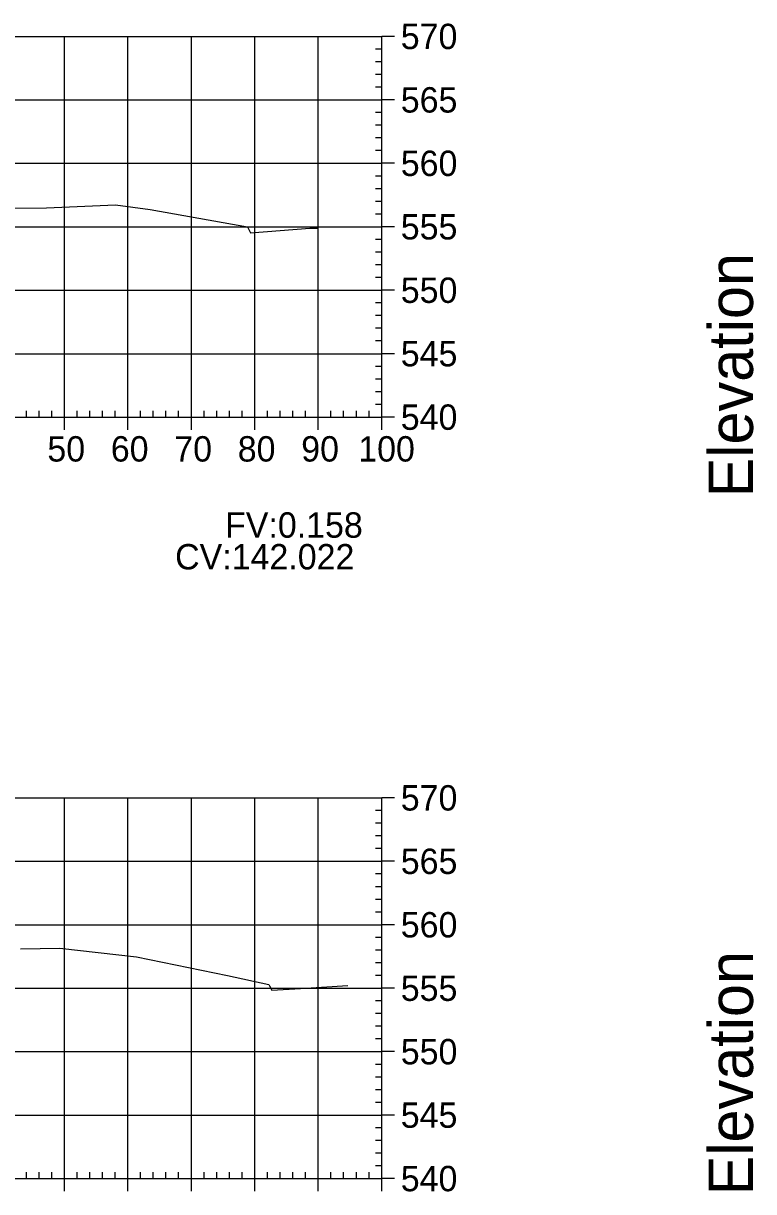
# Model space of a CAD drawing. Extents: x 704834 to 709892, y 372981 to 377533.
# Drawn here: x 707005.4 to 707120.5, y 373850.8 to 374034.9 of the extents above; entities that cross this region are included whole.
import ezdxf

# ---------------------------------------------------------------- set-up
doc = ezdxf.new("R2010")
doc.units = 0
for name, color, linetype in [('57', 7, 'Continuous'), ('59', 7, 'Continuous'), ('60', 7, 'Continuous'), ('Existing', 7, 'Continuous')]:
    doc.layers.add(name, color=color, linetype=linetype)

msp = doc.modelspace()

# ---------------------------------------------------------------- linework, layer by layer
at = {"layer": '57'}
for p, q in [((706861.87, 374032.82), (707061.87, 374032.82)), ((707011.87, 373972.82), (707011.87, 374032.82)), ((707021.87, 373972.82), (707021.87, 374032.82)), ((707031.87, 373972.82), (707031.87, 374032.82)), ((707041.87, 373972.82), (707041.87, 374032.82)), ((707051.87, 373972.82), (707051.87, 374032.82)), ((707061.87, 373972.82), (707061.87, 374032.82)), ((707061.87, 373972.82), (707061.87, 374032.82)), ((707063.87, 374032.82), (707061.87, 374032.82)), ((707061.87, 374030.82), (707060.87, 374030.82)), ((707061.87, 374028.82), (707060.87, 374028.82)), ((707061.87, 374026.82), (707060.87, 374026.82)), ((707061.87, 374024.82), (707060.87, 374024.82)), ((706861.87, 374022.82), (707061.87, 374022.82)), ((707063.87, 374022.82), (707061.87, 374022.82)), ((707061.87, 374020.82), (707060.87, 374020.82)), ((707061.87, 374018.82), (707060.87, 374018.82)), ((707061.87, 374016.82), (707060.87, 374016.82)), ((707061.87, 374014.82), (707060.87, 374014.82)), ((706861.87, 374012.82), (707061.87, 374012.82)), ((707063.87, 374012.82), (707061.87, 374012.82)), ((707061.87, 374010.82), (707060.87, 374010.82)), ((707061.87, 374008.82), (707060.87, 374008.82)), ((707061.87, 374006.82), (707060.87, 374006.82)), ((707061.87, 374004.82), (707060.87, 374004.82)), ((706861.87, 374002.82), (707061.87, 374002.82)), ((707063.87, 374002.82), (707061.87, 374002.82)), ((707061.87, 374000.82), (707060.87, 374000.82)), ((707061.87, 373998.82), (707060.87, 373998.82)), ((707061.87, 373996.82), (707060.87, 373996.82)), ((707061.87, 373994.82), (707060.87, 373994.82)), ((706861.87, 373992.82), (707061.87, 373992.82)), ((707063.87, 373992.82), (707061.87, 373992.82)), ((707061.87, 373990.82), (707060.87, 373990.82)), ((707061.87, 373988.82), (707060.87, 373988.82)), ((707061.87, 373986.82), (707060.87, 373986.82)), ((707061.87, 373984.82), (707060.87, 373984.82)), ((706861.87, 373982.82), (707061.87, 373982.82)), ((707063.87, 373982.82), (707061.87, 373982.82)), ((707061.87, 373980.82), (707060.87, 373980.82)), ((707061.87, 373978.82), (707060.87, 373978.82)), ((707061.87, 373976.82), (707060.87, 373976.82)), ((707005.87, 373972.82), (707005.87, 373973.82)), ((707007.87, 373972.82), (707007.87, 373973.82)), ((707009.87, 373972.82), (707009.87, 373973.82)), ((707013.87, 373972.82), (707013.87, 373973.82)), ((707015.87, 373972.82), (707015.87, 373973.82)), ((707017.87, 373972.82), (707017.87, 373973.82)), ((707019.87, 373972.82), (707019.87, 373973.82)), ((707023.87, 373972.82), (707023.87, 373973.82)), ((707025.87, 373972.82), (707025.87, 373973.82)), ((707027.87, 373972.82), (707027.87, 373973.82)), ((707029.87, 373972.82), (707029.87, 373973.82)), ((707033.87, 373972.82), (707033.87, 373973.82)), ((707035.87, 373972.82), (707035.87, 373973.82)), ((707037.87, 373972.82), (707037.87, 373973.82)), ((707039.87, 373972.82), (707039.87, 373973.82)), ((707043.87, 373972.82), (707043.87, 373973.82)), ((707045.87, 373972.82), (707045.87, 373973.82)), ((707047.87, 373972.82), (707047.87, 373973.82)), ((707049.87, 373972.82), (707049.87, 373973.82)), ((707053.87, 373972.82), (707053.87, 373973.82)), ((707055.87, 373972.82), (707055.87, 373973.82)), ((707057.87, 373972.82), (707057.87, 373973.82)), ((707059.87, 373972.82), (707059.87, 373973.82)), ((707061.87, 373974.82), (707060.87, 373974.82)), ((706861.87, 373972.82), (707061.87, 373972.82)), ((706861.87, 373972.82), (707061.87, 373972.82)), ((707011.87, 373970.82), (707011.87, 373972.82)), ((707021.87, 373970.82), (707021.87, 373972.82)), ((707031.87, 373970.82), (707031.87, 373972.82)), ((707041.87, 373970.82), (707041.87, 373972.82)), ((707051.87, 373970.82), (707051.87, 373972.82)), ((707061.87, 373970.82), (707061.87, 373972.82)), ((707063.87, 373972.82), (707061.87, 373972.82)), ((706861.87, 373912.82), (707061.87, 373912.82)), ((707011.87, 373852.82), (707011.87, 373912.82)), ((707021.87, 373852.82), (707021.87, 373912.82)), ((707031.87, 373852.82), (707031.87, 373912.82)), ((707041.87, 373852.82), (707041.87, 373912.82)), ((707051.87, 373852.82), (707051.87, 373912.82)), ((707061.87, 373852.82), (707061.87, 373912.82)), ((707061.87, 373852.82), (707061.87, 373912.82)), ((707063.87, 373912.82), (707061.87, 373912.82)), ((707061.87, 373910.82), (707060.87, 373910.82)), ((707061.87, 373908.82), (707060.87, 373908.82)), ((707061.87, 373906.82), (707060.87, 373906.82)), ((707061.87, 373904.82), (707060.87, 373904.82)), ((706861.87, 373902.82), (707061.87, 373902.82)), ((707063.87, 373902.82), (707061.87, 373902.82)), ((707061.87, 373900.82), (707060.87, 373900.82)), ((707061.87, 373898.82), (707060.87, 373898.82)), ((707061.87, 373896.82), (707060.87, 373896.82)), ((707061.87, 373894.82), (707060.87, 373894.82)), ((706861.87, 373892.82), (707061.87, 373892.82)), ((707063.87, 373892.82), (707061.87, 373892.82)), ((707061.87, 373890.82), (707060.87, 373890.82)), ((707061.87, 373888.82), (707060.87, 373888.82)), ((707061.87, 373886.82), (707060.87, 373886.82)), ((707061.87, 373884.82), (707060.87, 373884.82)), ((706861.87, 373882.82), (707061.87, 373882.82)), ((707063.87, 373882.82), (707061.87, 373882.82)), ((707061.87, 373880.82), (707060.87, 373880.82)), ((707061.87, 373878.82), (707060.87, 373878.82)), ((707061.87, 373876.82), (707060.87, 373876.82)), ((707061.87, 373874.82), (707060.87, 373874.82)), ((706861.87, 373872.82), (707061.87, 373872.82)), ((707063.87, 373872.82), (707061.87, 373872.82)), ((707061.87, 373870.82), (707060.87, 373870.82)), ((707061.87, 373868.82), (707060.87, 373868.82)), ((707061.87, 373866.82), (707060.87, 373866.82)), ((707061.87, 373864.82), (707060.87, 373864.82)), ((706861.87, 373862.82), (707061.87, 373862.82)), ((707063.87, 373862.82), (707061.87, 373862.82)), ((707061.87, 373860.82), (707060.87, 373860.82)), ((707061.87, 373858.82), (707060.87, 373858.82)), ((707061.87, 373856.82), (707060.87, 373856.82)), ((707061.87, 373854.82), (707060.87, 373854.82)), ((706861.87, 373852.82), (707061.87, 373852.82)), ((706861.87, 373852.82), (707061.87, 373852.82)), ((707005.87, 373852.82), (707005.87, 373853.82)), ((707007.87, 373852.82), (707007.87, 373853.82)), ((707009.87, 373852.82), (707009.87, 373853.82)), ((707011.87, 373850.82), (707011.87, 373852.82)), ((707013.87, 373852.82), (707013.87, 373853.82)), ((707015.87, 373852.82), (707015.87, 373853.82)), ((707017.87, 373852.82), (707017.87, 373853.82)), ((707019.87, 373852.82), (707019.87, 373853.82)), ((707021.87, 373850.82), (707021.87, 373852.82)), ((707023.87, 373852.82), (707023.87, 373853.82)), ((707025.87, 373852.82), (707025.87, 373853.82)), ((707027.87, 373852.82), (707027.87, 373853.82)), ((707029.87, 373852.82), (707029.87, 373853.82)), ((707031.87, 373850.82), (707031.87, 373852.82)), ((707033.87, 373852.82), (707033.87, 373853.82)), ((707035.87, 373852.82), (707035.87, 373853.82)), ((707037.87, 373852.82), (707037.87, 373853.82)), ((707039.87, 373852.82), (707039.87, 373853.82)), ((707041.87, 373850.82), (707041.87, 373852.82)), ((707043.87, 373852.82), (707043.87, 373853.82)), ((707045.87, 373852.82), (707045.87, 373853.82)), ((707047.87, 373852.82), (707047.87, 373853.82)), ((707049.87, 373852.82), (707049.87, 373853.82)), ((707051.87, 373850.82), (707051.87, 373852.82)), ((707053.87, 373852.82), (707053.87, 373853.82)), ((707055.87, 373852.82), (707055.87, 373853.82)), ((707057.87, 373852.82), (707057.87, 373853.82)), ((707059.87, 373852.82), (707059.87, 373853.82)), ((707061.87, 373850.82), (707061.87, 373852.82)), ((707063.87, 373852.82), (707061.87, 373852.82))]:
    msp.add_line(p, q, dxfattribs=at)
at = {"layer": 'Existing'}
for points in [[(706991.39, 374005.73), (707009.06, 374005.78), (707019.9, 374006.27), (707025.36, 374005.56), (707040.71, 374002.81), (707040.97, 374002.29), (707041.19, 374001.89), (707050.54, 374002.58), (707051.8, 374002.62), (707051.83, 374002.62)], [(707004.93, 373889.02), (707011.17, 373889.13), (707023.23, 373887.74), (707037.59, 373884.83), (707044.08, 373883.39), (707044.19, 373883.18), (707044.56, 373882.5), (707049.08, 373882.75), (707056.55, 373883.25)]]:
    msp.add_lwpolyline(points, dxfattribs=at)

# ---------------------------------------------------------------- texts
msp.add_text('CV:142.022', height=4).set_placement((707029.31, 373948.82))
at = {"layer": '57'}
for s, p in [('570', (707064.87, 374030.82)), ('565', (707064.87, 374020.82)), ('560', (707064.87, 374010.82)), ('555', (707064.87, 374000.82)), ('550', (707064.87, 373990.82)), ('545', (707064.87, 373980.82)), ('540', (707064.87, 373970.82)), ('50', (707009.18, 373965.82)), ('60', (707019.18, 373965.82)), ('70', (707029.18, 373965.82)), ('80', (707039.18, 373965.82)), ('90', (707049.18, 373965.82)), ('100', (707058.17, 373965.82)), ('570', (707064.87, 373910.82)), ('565', (707064.87, 373900.82)), ('560', (707064.87, 373890.82)), ('555', (707064.87, 373880.82)), ('550', (707064.87, 373870.82)), ('545', (707064.87, 373860.82)), ('540', (707064.87, 373850.82))]:
    msp.add_text(s, height=4, dxfattribs=at).set_placement(p)
at = {"layer": '59'}
msp.add_text('FV:0.158', height=4, dxfattribs=at).set_placement((707037.18, 373953.82))
at = {"layer": '60'}
for p in [(707120.37, 373960.18), (707120.37, 373850.18)]:
    msp.add_text('Elevation', height=7, rotation=90, dxfattribs=at).set_placement(p)

doc.saveas('drawing.dxf')
